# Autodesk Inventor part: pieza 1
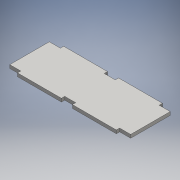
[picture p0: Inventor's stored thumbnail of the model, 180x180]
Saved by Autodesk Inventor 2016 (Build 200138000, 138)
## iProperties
Created: 2016-06
Part Number: pieza 1
Material: Genérico
Document SubType Name: Modeling
Designer: adm
Density: 1 g/cm^3
Appearance: Valor por defecto
Author: adm
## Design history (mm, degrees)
sketch "Boceto1"
  geometry: L1 (110, 0)-(110, -36); L2 (0, -36)-(0, 0); L3 (0, -36)-(10, -36); L4 (10, -36)-(10, -39); L5 (10, -39)-(50, -39); L6 (50, -39)-(50, -36); L7 (50, -36)-(60, -36); L8 (60, -36)-(60, -39); L9 (60, -39)-(100, -39); L10 (100, -39)-(100, -36); L11 (0, 0)-(10, 0); L12 (10, 0)-(10, 3); L13 (10, 3)-(50, 3); L14 (50, 3)-(50, 0); L15 (50, 0)-(60, 0); L16 (60, 0)-(60, 3); L17 (60, 3)-(100, 3); L18 (100, 3)-(100, 0); L19 (0, 0)-(10, 0); L20 (50, 0)-(60, 0); L21 (100, 0)-(110, 0); L22 (10, -36)-(0, -36); L23 (110, -36)-(100, -36); L24 (60, -36)-(50, -36)
  constraints: 48 end point, 26 perpendicular, 3 horizontal, 2 point on line
extrude "Extrusión1" new body sketch "Boceto1" distance "d15" = 3; taper "d16" = 0 deg
node "Sólido1"
